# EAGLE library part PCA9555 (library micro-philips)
16-bit I2C and SMBus I/O port with interrupt Source: PCA9555_5.pdf
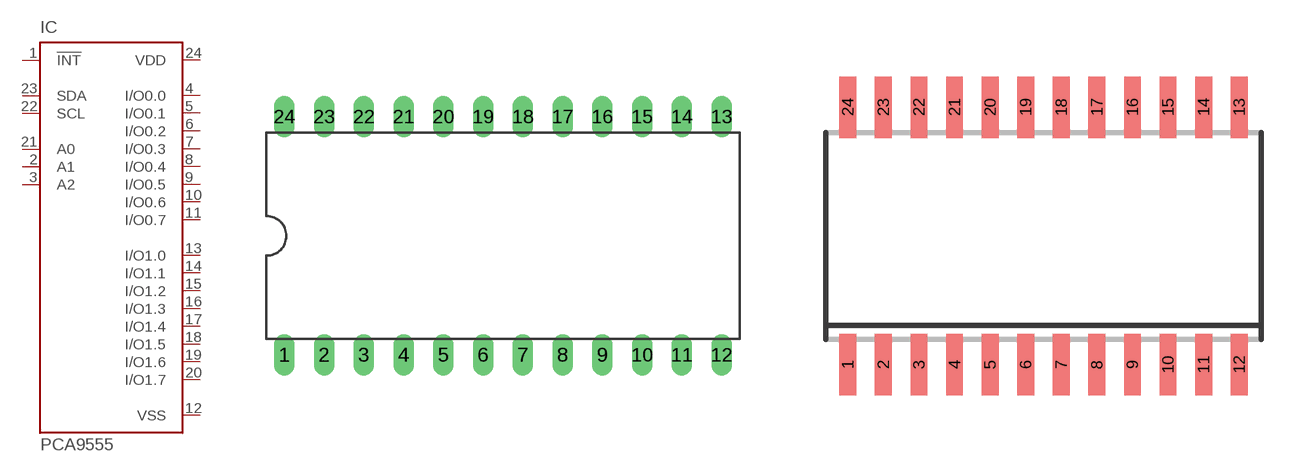
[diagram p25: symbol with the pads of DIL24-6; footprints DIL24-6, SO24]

Designator prefix IC

## PCA9555N (MPN: PCA9555N,112; OC_FARNELL: unknown; OC_NEWARK: 70R6677)  [DIL24-6]
1  !INT  out
2  A1  in
3  A2  in
4  I/O0.0
5  I/O0.1
6  I/O0.2
7  I/O0.3
8  I/O0.4
9  I/O0.5
10  I/O0.6
11  I/O0.7
12  VSS  pwr
13  I/O1.0
14  I/O1.1
15  I/O1.2
16  I/O1.3
17  I/O1.4
18  I/O1.5
19  I/O1.6
20  I/O1.7
21  A0  in
22  SCL  in
23  SDA
24  VDD  pwr

## PCA9555D (MPN: PCA9555DW; OC_FARNELL: 1408295; OC_NEWARK: 63K6067)  [SO24]
Pads as for DIL24-6

## PCA9555DB (MPN: PCA9555DB; OC_FARNELL: 1408295; OC_NEWARK: 63K6063)  [SSOP24]
Pads as for DIL24-6

## PCA9555BS (MPN: PCA9555BS,118; OC_FARNELL: 1575354; OC_NEWARK: 70R6671)  [HVQFN24]
1  I/O0.0
2  I/O0.1
3  I/O0.2
4  I/O0.3
5  I/O0.4
6  I/O0.5
7  I/O0.6
8  I/O0.7
9  VSS  pwr
10  I/O1.0
11  I/O1.1
12  I/O1.2
13  I/O1.3
14  I/O1.4
15  I/O1.5
16  I/O1.6
17  I/O1.7
18  A0  in
19  SCL  in
20  SDA
21  VDD  pwr
22  !INT  out
23  A1  in
24  A2  in

## PCA9555PW (MPN: PCA9555PW; OC_FARNELL: 1408297; OC_NEWARK: 63K6069)  [TSSOP24]
Pads as for DIL24-6

## Footprint DIL24-6 (pad centres in mm)
Dual In Line
drill 0.813 long: 1 -13.97,-7.62; 2 -11.43,-7.62; 3 -8.89,-7.62; 4 -6.35,-7.62; 5 -3.81,-7.62; 6 -1.27,-7.62; 7 1.27,-7.62; 8 3.81,-7.62; 9 6.35,-7.62; 10 8.89,-7.62; 11 11.43,-7.62; 12 13.97,-7.62; 13 13.97,7.62; 14 11.43,7.62; 15 8.89,7.62; 16 6.35,7.62; 17 3.81,7.62; 18 1.27,7.62; 19 -1.27,7.62; 20 -3.81,7.62; 21 -6.35,7.62; 22 -8.89,7.62; 23 -11.43,7.62; 24 -13.97,7.62

## Footprint SO24 (pad centres in mm)
Small Outline Package 7.6 x 15.74 mm
smd 0.6 x 2.2: 1 -6.985,-4.6; 2 -5.715,-4.6; 3 -4.445,-4.6; 4 -3.175,-4.6; 5 -1.905,-4.6; 6 -0.635,-4.6; 7 0.635,-4.6; 8 1.905,-4.6; 9 3.175,-4.6; 10 4.445,-4.6; 11 5.715,-4.6; 12 6.985,-4.6; 13 6.985,4.6; 14 5.715,4.6; 15 4.445,4.6; 16 3.175,4.6; 17 1.905,4.6; 18 0.635,4.6; 19 -0.635,4.6; 20 -1.905,4.6; 21 -3.175,4.6; 22 -4.445,4.6; 23 -5.715,4.6; 24 -6.985,4.6

## Footprint SSOP24 (pad centres in mm)
Small Shrink Outline Package SOT340-1 / JEDEC MO-150AG
smd 0.4 x 1.2: 1 -3.575,-3.42; 2 -2.925,-3.42; 3 -2.275,-3.42; 4 -1.625,-3.42; 5 -0.975,-3.42; 6 -0.325,-3.42; 7 0.325,-3.42; 8 0.975,-3.42; 9 1.625,-3.42; 10 2.275,-3.42; 11 2.925,-3.42; 12 3.575,-3.42; 13 3.575,3.42; 14 2.925,3.42; 15 2.275,3.42; 16 1.625,3.42; 17 0.975,3.42; 18 0.325,3.42; 19 -0.325,3.42; 20 -0.975,3.42; 21 -1.625,3.42; 22 -2.275,3.42; 23 -2.925,3.42; 24 -3.575,3.42

## Footprint HVQFN24 (pad centres in mm)
plastic thermal enhanced very thin quad flat package SOT616-1 no leads; 24 terminals; body 4 x 4 x 0.85 mm Source: PCA9555_5.pdf
smd 0.5 x 0.3: 1 -1.8,1.25; 2 -1.8,0.75; 3 -1.8,0.25; 4 -1.8,-0.25; 5 -1.8,-0.75; 6 -1.8,-1.25; 13 1.8,-1.25; 14 1.8,-0.75; 15 1.8,-0.25; 16 1.8,0.25; 17 1.8,0.75; 18 1.8,1.25
smd 0.3 x 0.5: 7 -1.25,-1.8; 8 -0.75,-1.8; 9 -0.25,-1.8; 10 0.25,-1.8; 11 0.75,-1.8; 12 1.25,-1.8; 19 1.25,1.8; 20 0.75,1.8; 21 0.25,1.8; 22 -0.25,1.8; 23 -0.75,1.8; 24 -1.25,1.8
smd 2.25 x 2.25: TH 0,0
